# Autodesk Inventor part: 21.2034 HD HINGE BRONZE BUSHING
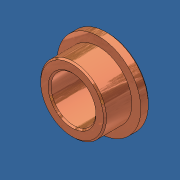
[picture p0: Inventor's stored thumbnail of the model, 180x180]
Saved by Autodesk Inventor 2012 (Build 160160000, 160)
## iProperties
Created: 2014-05
Part Number: 21.2034 HD HINGE BRONZE BUSHING
Material: Bronze, Soft Tin
Document SubType Name: Modeling
Designer: Admin
Density: 8.874 g/cm^3
Mass: 27.6555 g
Surface Area: 22.5588 cm^2
Volume: 3.11646 cm^3
Author: Admin
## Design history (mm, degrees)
node "Product1"
node "Base1"
body "Solid1"
